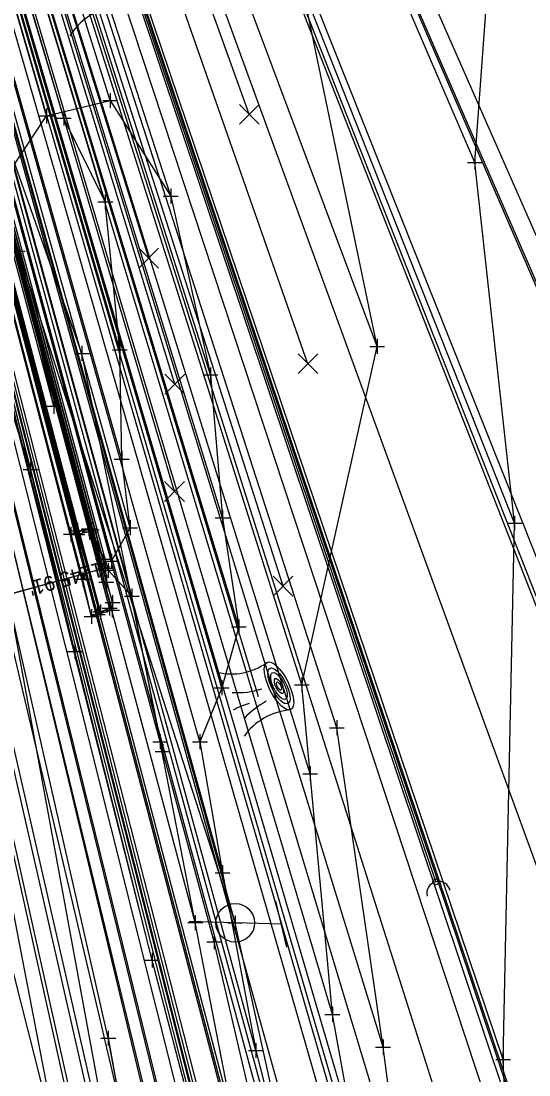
# Model space of a CAD drawing. Extents: x 125846 to 132549, y 511012 to 513420.
# Drawn here: x 127023.8 to 127058, y 512060.5 to 512131.4 of the extents above; entities that cross this region are included whole.
import ezdxf

# ---------------------------------------------------------------- set-up
doc = ezdxf.new("R2010")
doc.units = 0
for name, color, linetype in [('Default', 7, 'Continuous'), ('DR_X_Ditch', 7, 'Continuous'), ('DR_X_Elev_Flow', 7, 'Continuous'), ('DR_X_Headwall', 7, 'Continuous'), ('DR_X_Storm_Sewer', 7, 'Continuous'), ('DT_X_Island', 7, 'Continuous'), ('DT_X_Terrain_Boundary', 7, 'Continuous'), ('PM_X_Edge_Line', 7, 'Continuous'), ('PV_X_EOP', 7, 'Continuous'), ('PV_X_Shoulder_Aggregate', 7, 'Continuous'), ('SC_Scratch1', 7, 'Continuous'), ('SV_Observation', 7, 'Continuous'), ('SV_X_Break_Lines', 7, 'Continuous'), ('UT_X_Gas', 7, 'Continuous'), ('UT_X_Overhead_Cable_TV', 7, 'Continuous'), ('UT_X_Overhead_Telecom', 7, 'Continuous'), ('UT_X_Sanitary_Line', 7, 'Continuous'), ('UT_X_Water', 7, 'Continuous')]:
    doc.layers.add(name, color=color, linetype=linetype)

msp = doc.modelspace()

# ---------------------------------------------------------------- linework, layer by layer
at = {"layer": 'Default'}
msp.add_lwpolyline([(127029.318, 512094.537), (126965.937, 512077.201)], dxfattribs=at)
at = {"layer": 'DR_X_Ditch'}
for points in [[(127029.911, 512095.06), (127031.171, 512097.313), (127030.607, 512101.934), (127030.479, 512109.274), (127029.504, 512119.246), (127026.706, 512124.88)], [(127038.171, 512057.207), (127035.555, 512070.731), (127033.191, 512082.91), (127031.286, 512092.711), (127029.701, 512094.446)]]:
    msp.add_lwpolyline(points, dxfattribs=at)
at = {"layer": 'DR_X_Elev_Flow'}
for p, q in [((127029.801, 512094.67), (127028.836, 512094.404)), ((127029.186, 512095.019), (127029.451, 512094.055)), ((127029.318, 512094.537), (127029.318, 512094.537))]:
    msp.add_line(p, q, dxfattribs=at)
at = {"layer": 'DR_X_Headwall'}
msp.add_lwpolyline([(127029.178, 512091.644), (127029.792, 512091.899), (127028.447, 512097.024), (127027.627, 512096.847)], close=True, dxfattribs=at)
at = {"layer": 'DR_X_Storm_Sewer'}
msp.add_line((127029.318, 512094.537), (126965.937, 512077.201), dxfattribs=at)
at = {"layer": 'DT_X_Island'}
msp.add_line((127039.821, 512085.917), (127039.821, 512085.917), dxfattribs=at)
for centre, radius, start, end in [((127030.777, 512128.16), 4.292, 99.87323, 148.38201), ((127038.024, 512091.476), 4.003, 256.04736, 305.4405), ((127038.463, 512091.265), 5.053, 265.30737, 288.06168), ((127040.025, 512081.936), 3.639, 103.30624, 121.63602), ((127043.443, 512080.132), 6.319, 119.4789, 136.6352), ((127042.33, 512080.776), 4.292, 95.92422, 144.43299)]:
    msp.add_arc(centre, radius, start, end, dxfattribs=at)
for major_axis in [(0.798, -1.587), (0.599, -1.19), (0.449, -0.892), (0.253, -0.502), (0.142, -0.282)]:
    msp.add_ellipse((127041.19, 512086.659), major_axis=major_axis, ratio=0.36865, dxfattribs=at)
at = {"layer": 'DT_X_Terrain_Boundary'}
msp.add_circle((127051.751, 512073.478), 0.2, dxfattribs=at)
msp.add_arc((127051.935, 512072.7), 0.8, 13.30624, 193.30624, dxfattribs=at)
at = {"layer": 'PM_X_Edge_Line'}
msp.add_lwpolyline([(127129.076, 511490.895), (127116.455, 511533.23), (127105.518, 511573.347), (127095.102, 511617.805), (127085.545, 511662.999), (127078.204, 511707.058), (127071.722, 511751.053), (127065.474, 511797.182), (127059.956, 511837.919), (127054.704, 511874.757), (127049.142, 511916.211), (127043.547, 511954.034), (127036.991, 511996.704), (127033.246, 512019.325), (127025.208, 512059.915), (127017.371, 512090.859), (127007.161, 512124.475), (127003.544, 512134.635), (126991.35, 512165.92), (126978.354, 512195.342)], dxfattribs=at)
at = {"layer": 'PV_X_EOP'}
msp.add_lwpolyline([(127037.881, 512019.282), (127029.702, 512062.957), (127023.055, 512092.199), (127012.397, 512127.764), (127009.4, 512137.026), (126996.87, 512167.973), (126984.43, 512195.874), (126972.834, 512218.045), (126964.85, 512234.205), (126954.019, 512254.154), (126946.281, 512268.482), (126939.955, 512279.025), (126918.506, 512314.814), (126894.741, 512355.014), (126873.069, 512391.797), (126850.03, 512430.621), (126826.944, 512469.558), (126798.525, 512517.081)], dxfattribs=at)
at = {"layer": 'PV_X_Shoulder_Aggregate'}
msp.add_lwpolyline([(127141.173, 511493.84), (127130.336, 511535.339), (127119.754, 511578.037), (127109.763, 511621.385), (127097.276, 511671.585), (127090.679, 511708.746), (127082.392, 511755.119), (127074.354, 511798.182), (127068.621, 511838.498), (127063.466, 511875.476), (127057.825, 511918.301), (127051.974, 511956.972), (127044.882, 511998.394), (127045.401, 512019.771), (127041.13, 512035.7), (127032.647, 512068.207), (127027.45, 512088.978), (127024.481, 512101.231), (127012.345, 512138.661), (127000.22, 512169.62), (126990.564, 512194.834), (126991.95, 512202.796)], dxfattribs=at)
at = {"layer": 'SV_Observation'}
for p, q in [((127045.401, 512019.771), (126968.531, 512321.464)), ((127041.13, 512035.7), (126968.531, 512321.464)), ((127032.647, 512068.207), (126968.531, 512321.464)), ((127027.45, 512088.978), (126968.531, 512321.464)), ((127024.481, 512101.231), (126968.531, 512321.464)), ((127073.552, 511921.266), (126968.531, 512321.464)), ((127071.047, 511921.921), (126968.531, 512321.464)), ((127066.989, 511921.901), (126968.531, 512321.464)), ((127060.048, 511920.088), (126968.531, 512321.464)), ((127065.863, 511933.887), (126968.531, 512321.464)), ((127073.951, 511941.541), (126968.531, 512321.464)), ((127066.822, 511947.549), (126968.531, 512321.464)), ((127069.51, 511949.557), (126968.531, 512321.464)), ((127057.432, 511955.351), (126968.531, 512321.464)), ((127059.125, 511953.266), (126968.531, 512321.464)), ((127053.246, 511952.158), (126968.531, 512321.464)), ((127053.206, 511989.442), (126968.531, 512321.464)), ((127065.109, 511990.276), (126968.531, 512321.464)), ((127078.572, 511992.931), (126968.531, 512321.464)), ((127076.98, 511999.287), (126968.531, 512321.464)), ((127068.16, 512025.122), (126968.531, 512321.464)), ((127057.836, 512025.141), (126968.531, 512321.464)), ((127081.349, 512033.743), (126968.531, 512321.464)), ((127075.998, 512026.596), (126968.531, 512321.464)), ((127071.419, 512059.846), (126968.531, 512321.464)), ((127056.272, 512061.509), (126968.531, 512321.464)), ((127054.169, 512023.704), (126968.531, 512321.464)), ((127051.19, 512039.694), (126968.531, 512321.464)), ((127048.191, 512062.36), (126968.531, 512321.464)), ((127045.083, 512083.851), (126968.531, 512321.464)), ((127038.171, 512057.207), (126968.531, 512321.464)), ((127035.555, 512070.731), (126968.531, 512321.464)), ((127033.191, 512082.91), (126968.531, 512321.464)), ((127031.286, 512092.711), (126968.531, 512321.464)), ((127029.701, 512094.446), (126968.531, 512321.464)), ((127029.911, 512095.06), (126968.531, 512321.464)), ((127031.171, 512097.313), (126968.531, 512321.464)), ((127030.607, 512101.934), (126968.531, 512321.464)), ((127030.479, 512109.274), (126968.531, 512321.464)), ((127029.504, 512119.246), (126968.531, 512321.464)), ((127026.706, 512124.88), (126968.531, 512321.464)), ((127026.032, 512105.486), (126968.531, 512321.464)), ((127025.552, 512125.024), (126968.531, 512321.464)), ((127029.829, 512126.065), (126968.531, 512321.464)), ((127033.906, 512119.635), (126968.531, 512321.464)), ((127036.586, 512107.591), (126968.531, 512321.464)), ((127037.392, 512097.983), (126968.531, 512321.464)), ((127038.484, 512090.629), (126968.531, 512321.464)), ((127037.338, 512086.543), (126968.531, 512321.464)), ((127035.871, 512082.909), (126968.531, 512321.464)), ((127037.388, 512074.091), (126968.531, 512321.464)), ((127039.631, 512062.129), (126968.531, 512321.464)), ((127043.913, 512045.3), (126968.531, 512321.464)), ((127047.537, 512049.429), (126968.531, 512321.464)), ((127044.785, 512064.555), (126968.531, 512321.464)), ((127043.288, 512080.755), (126968.531, 512321.464)), ((127042.728, 512086.745), (126968.531, 512321.464)), ((127047.796, 512109.512), (126968.531, 512321.464)), ((127039.193, 512125.134), (126968.531, 512321.464)), ((127043.139, 512108.347), (126968.531, 512321.464)), ((127041.464, 512093.379), (126968.531, 512321.464)), ((127034.158, 512099.75), (126968.531, 512321.464)), ((127034.182, 512106.966), (126968.531, 512321.464)), ((127032.424, 512115.455), (126968.531, 512321.464)), ((127039.821, 512085.917), (126968.531, 512321.464)), ((127051.751, 512073.478), (126968.531, 512321.464)), ((127052.165, 512057.881), (126968.531, 512321.464)), ((127069.93, 512090.98), (126968.531, 512321.464)), ((127057.033, 512097.618), (126968.531, 512321.464)), ((127054.373, 512121.887), (126968.531, 512321.464)), ((127059.428, 512111.391), (126968.531, 512321.464)), ((127061.873, 512086.857), (126968.531, 512321.464)), ((127079.014, 512066.519), (126968.531, 512321.464)), ((127056.352, 512055.138), (126968.531, 512321.464)), ((127029.178, 512091.644), (126968.531, 512321.464)), ((127029.792, 512091.899), (126968.531, 512321.464)), ((127028.447, 512097.024), (126968.531, 512321.464)), ((127027.627, 512096.847), (126968.531, 512321.464)), ((127027.189, 512096.875), (126968.531, 512321.464)), ((127027.634, 512097.107), (126968.531, 512321.464)), ((127028.403, 512097.244), (126968.531, 512321.464)), ((127028.581, 512097.163), (126968.531, 512321.464)), ((127029.354, 512095.189), (126968.531, 512321.464)), ((127029.495, 512094.587), (126968.531, 512321.464)), ((127029.574, 512093.645), (126968.531, 512321.464)), ((127029.995, 512092.279), (126968.531, 512321.464)), ((127029.963, 512091.767), (126968.531, 512321.464)), ((127028.986, 512091.475), (126968.531, 512321.464)), ((127028.583, 512091.332), (126968.531, 512321.464)), ((127027.991, 512093.85), (126968.531, 512321.464)), ((127029.318, 512094.537), (126968.531, 512321.464)), ((127038.245, 512070.716), (126968.531, 512321.464)), ((127038.245, 512070.716), (126968.531, 512321.464)), ((127038.245, 512070.716), (126968.531, 512321.464)), ((127071.139, 511920.25), (126968.531, 512321.464)), ((127071.139, 511920.25), (126968.531, 512321.464)), ((127071.139, 511920.25), (126968.531, 512321.464)), ((127100.367, 511762.141), (126968.531, 512321.464)), ((127100.367, 511762.141), (126968.531, 512321.464)), ((127100.367, 511762.141), (126968.531, 512321.464)), ((127120.309, 511642.52), (126968.531, 512321.464)), ((127120.309, 511642.52), (126968.531, 512321.464)), ((127120.309, 511642.52), (126968.531, 512321.464)), ((127151.135, 511501.172), (126968.531, 512321.464)), ((127151.135, 511501.172), (126968.531, 512321.464)), ((127151.135, 511501.172), (126968.531, 512321.464)), ((127012.397, 512127.764), (127096.904, 511691.052)), ((127023.055, 512092.199), (127096.904, 511691.052)), ((127029.702, 512062.957), (127096.904, 511691.052))]:
    msp.add_line(p, q, dxfattribs=at)
at = {"layer": 'SV_X_Break_Lines'}
for points in [[(127047.537, 512049.429), (127044.785, 512064.555), (127043.288, 512080.755), (127042.728, 512086.745), (127047.796, 512109.512), (127042.611, 512134.435), (127037.104, 512153.118), (127027.665, 512172.611), (127020.703, 512190.324), (127013.729, 512206.525)], [(127060.048, 511920.088), (127057.432, 511955.351), (127053.206, 511989.442), (127057.836, 512025.141), (127056.272, 512061.509), (127057.033, 512097.618), (127054.373, 512121.887), (127056.828, 512155.642), (127054.273, 512169.243), (127038.647, 512183.232), (127024.37, 512187.705)], [(127023.191, 512121.469), (127025.552, 512125.024), (127029.829, 512126.065), (127033.906, 512119.635), (127036.586, 512107.591), (127037.392, 512097.983), (127038.484, 512090.629), (127037.338, 512086.543), (127035.871, 512082.909), (127037.388, 512074.091), (127039.631, 512062.129), (127043.913, 512045.3)], [(127026.032, 512105.486), (127023.607, 512115.926), (127021.276, 512125.331)], [(127054.169, 512023.704), (127051.19, 512039.694), (127048.191, 512062.36), (127045.083, 512083.851)]]:
    msp.add_lwpolyline(points, dxfattribs=at)
msp.add_lwpolyline([(127027.189, 512096.875), (127027.634, 512097.107), (127028.403, 512097.244), (127028.581, 512097.163), (127029.354, 512095.189), (127029.495, 512094.587), (127029.574, 512093.645), (127029.995, 512092.279), (127029.963, 512091.767), (127028.986, 512091.475), (127028.583, 512091.332), (127027.991, 512093.85)], close=True, dxfattribs=at)
at = {"layer": 'UT_X_Gas'}
for p, q in [((127041.718, 512069.069), (127040.98, 512072.183)), ((127041.349, 512070.626), (127035.14, 512070.805))]:
    msp.add_line(p, q, dxfattribs=at)
msp.add_circle((127038.245, 512070.716), 1.3, dxfattribs=at)
at = {"layer": 'UT_X_Overhead_Cable_TV'}
msp.add_lwpolyline([(127151.135, 511501.172), (127120.309, 511642.52), (127100.367, 511762.141), (127071.139, 511920.25), (127038.245, 512070.716), (126995.9, 512201.988), (126951.927, 512290.638), (126888.078, 512393.934), (126821.569, 512508.62), (126750.649, 512627.876), (126677.44, 512750.383), (126606.516, 512869.514), (126525.52, 513001.821), (126518.89, 513012.818), (126445.697, 513128.427), (126355.465, 513218.249), (126225.896, 513304.994), (126163.086, 513330.602), (126019.813, 513381.694)], dxfattribs=at)
at = {"layer": 'UT_X_Overhead_Telecom'}
msp.add_lwpolyline([(127151.135, 511501.172), (127120.309, 511642.52), (127100.367, 511762.141), (127071.139, 511920.25), (127038.245, 512070.716), (126995.9, 512201.988), (126951.927, 512290.638), (126888.078, 512393.934), (126821.569, 512508.62), (126750.649, 512627.876), (126677.44, 512750.383), (126606.516, 512869.514), (126525.52, 513001.821), (126518.89, 513012.818), (126445.697, 513128.427), (126354.464, 513218.752), (126225.896, 513304.994), (126163.086, 513330.602), (126019.813, 513381.694)], dxfattribs=at)
at = {"layer": 'UT_X_Sanitary_Line'}
for p, q in [((127029.329, 512126.065), (127030.329, 512126.065)), ((127029.829, 512126.565), (127029.829, 512125.565)), ((127029.829, 512126.065), (127029.829, 512126.065)), ((127025.552, 512125.524), (127025.552, 512124.524)), ((127026.706, 512125.38), (127026.706, 512124.38)), ((127025.052, 512125.024), (127026.052, 512125.024)), ((127025.552, 512125.024), (127025.552, 512125.024)), ((127026.206, 512124.88), (127027.206, 512124.88)), ((127026.706, 512124.88), (127026.706, 512124.88)), ((127054.373, 512122.387), (127054.373, 512121.387)), ((127053.873, 512121.887), (127054.873, 512121.887)), ((127054.373, 512121.887), (127054.373, 512121.887)), ((127029.504, 512119.746), (127029.504, 512118.746)), ((127033.406, 512119.635), (127034.406, 512119.635)), ((127033.906, 512120.135), (127033.906, 512119.135)), ((127033.906, 512119.635), (127033.906, 512119.635)), ((127029.004, 512119.246), (127030.004, 512119.246)), ((127029.504, 512119.246), (127029.504, 512119.246)), ((127023.107, 512115.926), (127024.107, 512115.926)), ((127030.479, 512109.774), (127030.479, 512108.774)), ((127047.796, 512110.012), (127047.796, 512109.012)), ((127027.423, 512109.043), (127028.423, 512109.043)), ((127027.923, 512109.543), (127027.923, 512108.543)), ((127027.923, 512109.043), (127027.923, 512109.043)), ((127029.979, 512109.274), (127030.979, 512109.274)), ((127030.479, 512109.274), (127030.479, 512109.274)), ((127047.296, 512109.512), (127048.296, 512109.512)), ((127047.796, 512109.512), (127047.796, 512109.512)), ((127036.086, 512107.591), (127037.086, 512107.591)), ((127036.586, 512108.091), (127036.586, 512107.091)), ((127036.586, 512107.591), (127036.586, 512107.591)), ((127025.532, 512105.486), (127026.532, 512105.486)), ((127026.032, 512105.986), (127026.032, 512104.986)), ((127026.032, 512105.486), (127026.032, 512105.486)), ((127030.107, 512101.934), (127031.107, 512101.934)), ((127030.607, 512102.434), (127030.607, 512101.434)), ((127030.607, 512101.934), (127030.607, 512101.934)), ((127023.981, 512101.231), (127024.981, 512101.231)), ((127024.481, 512101.731), (127024.481, 512100.731)), ((127024.481, 512101.231), (127024.481, 512101.231)), ((127037.392, 512098.483), (127037.392, 512097.483)), ((127027.634, 512097.607), (127027.634, 512096.607)), ((127028.403, 512097.744), (127028.403, 512096.744)), ((127028.447, 512097.524), (127028.447, 512096.524)), ((127028.581, 512097.663), (127028.581, 512096.663)), ((127031.171, 512097.813), (127031.171, 512096.813)), ((127036.892, 512097.983), (127037.892, 512097.983)), ((127037.392, 512097.983), (127037.392, 512097.983)), ((127056.533, 512097.618), (127057.533, 512097.618)), ((127057.033, 512098.118), (127057.033, 512097.118)), ((127057.033, 512097.618), (127057.033, 512097.618)), ((127026.689, 512096.875), (127027.689, 512096.875)), ((127027.127, 512096.847), (127028.127, 512096.847)), ((127027.134, 512097.107), (127028.134, 512097.107)), ((127027.189, 512097.375), (127027.189, 512096.375)), ((127027.189, 512096.875), (127027.189, 512096.875)), ((127027.627, 512097.347), (127027.627, 512096.347)), ((127027.627, 512096.847), (127027.627, 512096.847)), ((127027.634, 512097.107), (127027.634, 512097.107)), ((127027.903, 512097.244), (127028.903, 512097.244)), ((127027.947, 512097.024), (127028.947, 512097.024)), ((127028.081, 512097.163), (127029.081, 512097.163)), ((127028.403, 512097.244), (127028.403, 512097.244)), ((127028.447, 512097.024), (127028.447, 512097.024)), ((127028.581, 512097.163), (127028.581, 512097.163)), ((127030.671, 512097.313), (127031.671, 512097.313)), ((127031.171, 512097.313), (127031.171, 512097.313)), ((127029.354, 512095.689), (127029.354, 512094.689)), ((127029.911, 512095.56), (127029.911, 512094.56)), ((127028.854, 512095.189), (127029.854, 512095.189)), ((127029.354, 512095.189), (127029.354, 512095.189)), ((127029.411, 512095.06), (127030.411, 512095.06)), ((127029.495, 512095.087), (127029.495, 512094.087)), ((127029.701, 512094.946), (127029.701, 512093.946)), ((127029.911, 512095.06), (127029.911, 512095.06)), ((127027.991, 512094.35), (127027.991, 512093.35)), ((127028.995, 512094.587), (127029.995, 512094.587)), ((127029.201, 512094.446), (127030.201, 512094.446)), ((127029.495, 512094.587), (127029.495, 512094.587)), ((127029.574, 512094.145), (127029.574, 512093.145)), ((127029.701, 512094.446), (127029.701, 512094.446)), ((127027.491, 512093.85), (127028.491, 512093.85)), ((127027.991, 512093.85), (127027.991, 512093.85)), ((127029.074, 512093.645), (127030.074, 512093.645)), ((127029.574, 512093.645), (127029.574, 512093.645)), ((127029.995, 512092.779), (127029.995, 512091.779)), ((127030.786, 512092.711), (127031.786, 512092.711)), ((127031.286, 512093.211), (127031.286, 512092.211)), ((127031.286, 512092.711), (127031.286, 512092.711)), ((127028.583, 512091.832), (127028.583, 512090.832)), ((127028.986, 512091.975), (127028.986, 512090.975)), ((127029.178, 512092.144), (127029.178, 512091.144)), ((127029.292, 512091.899), (127030.292, 512091.899)), ((127029.495, 512092.279), (127030.495, 512092.279)), ((127029.792, 512092.399), (127029.792, 512091.399)), ((127029.792, 512091.899), (127029.792, 512091.899)), ((127029.963, 512092.267), (127029.963, 512091.267)), ((127029.995, 512092.279), (127029.995, 512092.279)), ((127028.083, 512091.332), (127029.083, 512091.332)), ((127028.486, 512091.475), (127029.486, 512091.475)), ((127028.583, 512091.332), (127028.583, 512091.332)), ((127028.678, 512091.644), (127029.678, 512091.644)), ((127028.986, 512091.475), (127028.986, 512091.475)), ((127029.178, 512091.644), (127029.178, 512091.644)), ((127029.463, 512091.767), (127030.463, 512091.767)), ((127029.963, 512091.767), (127029.963, 512091.767)), ((127038.484, 512091.129), (127038.484, 512090.129)), ((127037.984, 512090.629), (127038.984, 512090.629)), ((127038.484, 512090.629), (127038.484, 512090.629)), ((127027.45, 512089.478), (127027.45, 512088.478)), ((127026.95, 512088.978), (127027.95, 512088.978)), ((127027.45, 512088.978), (127027.45, 512088.978)), ((127037.338, 512087.043), (127037.338, 512086.043)), ((127042.728, 512087.245), (127042.728, 512086.245)), ((127036.838, 512086.543), (127037.838, 512086.543)), ((127037.338, 512086.543), (127037.338, 512086.543)), ((127042.228, 512086.745), (127043.228, 512086.745)), ((127042.728, 512086.745), (127042.728, 512086.745)), ((127045.083, 512084.351), (127045.083, 512083.351)), ((127033.191, 512083.41), (127033.191, 512082.41)), ((127035.871, 512083.409), (127035.871, 512082.409)), ((127044.583, 512083.851), (127045.583, 512083.851)), ((127045.083, 512083.851), (127045.083, 512083.851)), ((127032.691, 512082.91), (127033.691, 512082.91)), ((127033.191, 512082.91), (127033.191, 512082.91)), ((127033.367, 512082.745), (127033.367, 512081.745)), ((127035.371, 512082.909), (127036.371, 512082.909)), ((127035.871, 512082.909), (127035.871, 512082.909)), ((127032.867, 512082.245), (127033.867, 512082.245)), ((127033.367, 512082.245), (127033.367, 512082.245)), ((127043.288, 512081.255), (127043.288, 512080.255)), ((127042.788, 512080.755), (127043.788, 512080.755)), ((127043.288, 512080.755), (127043.288, 512080.755)), ((127036.888, 512074.091), (127037.888, 512074.091)), ((127037.388, 512074.591), (127037.388, 512073.591)), ((127037.388, 512074.091), (127037.388, 512074.091)), ((127035.055, 512070.731), (127036.055, 512070.731)), ((127035.555, 512071.231), (127035.555, 512070.231)), ((127035.555, 512070.731), (127035.555, 512070.731)), ((127037.745, 512070.716), (127038.745, 512070.716)), ((127037.745, 512070.716), (127038.745, 512070.716)), ((127038.245, 512071.216), (127038.245, 512070.216)), ((127038.245, 512071.216), (127038.245, 512070.216)), ((127038.245, 512070.716), (127038.245, 512070.716)), ((127038.245, 512070.716), (127038.245, 512070.716)), ((127036.829, 512069.942), (127036.829, 512068.942)), ((127036.329, 512069.442), (127037.329, 512069.442)), ((127036.829, 512069.442), (127036.829, 512069.442)), ((127032.647, 512068.707), (127032.647, 512067.707)), ((127032.147, 512068.207), (127033.147, 512068.207)), ((127032.647, 512068.207), (127032.647, 512068.207)), ((127044.785, 512065.055), (127044.785, 512064.055)), ((127044.285, 512064.555), (127045.285, 512064.555)), ((127044.785, 512064.555), (127044.785, 512064.555)), ((127029.702, 512063.457), (127029.702, 512062.457)), ((127029.202, 512062.957), (127030.202, 512062.957)), ((127029.702, 512062.957), (127029.702, 512062.957)), ((127048.191, 512062.86), (127048.191, 512061.86)), ((127039.131, 512062.129), (127040.131, 512062.129)), ((127039.631, 512062.629), (127039.631, 512061.629)), ((127039.631, 512062.129), (127039.631, 512062.129)), ((127047.691, 512062.36), (127048.691, 512062.36)), ((127048.191, 512062.36), (127048.191, 512062.36)), ((127055.772, 512061.509), (127056.772, 512061.509)), ((127056.272, 512062.009), (127056.272, 512061.009)), ((127056.272, 512061.509), (127056.272, 512061.509))]:
    msp.add_line(p, q, dxfattribs=at)
at = {"layer": 'UT_X_Water'}
for p, q in [((127038.527, 512124.466), (127039.86, 512125.801)), ((127038.527, 512125.801), (127039.86, 512124.466)), ((127031.757, 512114.788), (127033.09, 512116.123)), ((127031.757, 512116.123), (127033.09, 512114.788)), ((127042.472, 512107.679), (127043.806, 512109.014)), ((127042.472, 512109.014), (127043.806, 512107.679)), ((127033.516, 512106.299), (127034.849, 512107.634)), ((127033.516, 512107.634), (127034.849, 512106.299)), ((127033.491, 512099.082), (127034.825, 512100.417)), ((127033.491, 512100.417), (127034.825, 512099.082)), ((127040.798, 512092.711), (127042.131, 512094.046)), ((127040.798, 512094.046), (127042.131, 512092.711))]:
    msp.add_line(p, q, dxfattribs=at)
for points in [[(127120.897, 511538.029), (127108.138, 511584.202), (127099.503, 511621.164), (127090.048, 511669.514), (127082.171, 511717.385), (127073.574, 511775.056), (127066.81, 511829.446), (127058.814, 511888.602), (127043.406, 511993.442), (127034.289, 512050.048), (127018.031, 512117.781), (127000.658, 512166.916), (126987.6, 512201.022), (126978.137, 512226.33), (126958.939, 512269.795)], [(127130.237, 511540.801), (127118.853, 511585.529), (127110.538, 511618.994), (127105.749, 511669.258), (127105.463, 511678.853), (127100.187, 511715.498), (127088.347, 511775.172), (127083.291, 511824.102), (127067.07, 511903.767), (127055.765, 511988.379), (127036.829, 512069.442), (127033.367, 512082.245), (127027.923, 512109.043), (127002.169, 512181.974), (126993.16, 512202.119), (126987.943, 512215.623), (126977.802, 512240.129), (126981.164, 512262.259), (126983.111, 512266.558), (127000.797, 512269.377)]]:
    msp.add_lwpolyline(points, dxfattribs=at)

# ---------------------------------------------------------------- texts
at = {"layer": 'SC_Scratch1'}
msp.add_text("1245.91'", height=1, rotation=195.29723, dxfattribs=at).set_placement((127029.187, 512095.019))

doc.saveas('drawing.dxf')
